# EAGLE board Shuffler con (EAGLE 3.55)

Size 83.49 x 51.42 mm. Coordinates in mm from the lower left corner, seen from the top.
Outline: 43.02,26.03 43.02,27.3
Outline: 43.02,27.3 44.29,27.3 43.02,28.57
Outline: 43.02,28.57 41.75,27.3 43.02,27.3
Outline: 44.29,28.57 43.02,28.57
Outline: 43.02,28.57 41.75,28.57
Outline: 43.02,28.57 43.02,29.84
Outline: 0,0 83.49,0 83.49,51.42 0,51.42 0,0
Outline: 67.78,1.9 67.78,6.98 77.94,6.98 77.94,22.86 66.51,22.86 66.51,29.21 55.08,29.21 55.08,1.9 67.78,1.9
Copper layers used: 

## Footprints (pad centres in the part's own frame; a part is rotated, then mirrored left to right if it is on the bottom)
_PCB = drill 1.016 pad 1.93 square: 0 -5.08,10.16; 1 -2.54,10.16; 2 2.54,10.16; 3 5.08,10.16;  0,0;  -5.08,-2.54;  -7.62,0;  5.08,-2.54;  7.62,0
04-1 = drill 0.813 pad 1.6 octagon:  -3.81,0;  -1.27,0;  1.27,0;  3.81,0
02-1 = drill 0.813 pad 1.6 octagon:  -1.27,0;  1.27,0
03-1 = drill 0.813 pad 1.6 octagon:  -2.54,0;  0,0;  2.54,0
01-1 = drill 0.813 pad 1.6 octagon:  0,0
02-1' = drill 1.016 pad 1.6 round:  -1.27,0 | drill 1.016 pad 1.6 octagon:  1.27,0

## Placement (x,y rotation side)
DIN1  DIN 5p  [_PCB]  11.9,39.36 0 top
DIN2  DIN 5p  [_PCB]  72.86,39.36 0 top
DIN3  DIN 5p  [_PCB]  32.22,39.36 0 top
SV1  FE04-1  [04-1]  60.16,7.61 270 top
SV2  FE04-1  [04-1]  33.49,1.27 180 top
SV3  FE04-1  [04-1]  62.7,22.86 270 top
SV4  FE04-1  [04-1]  75.4,15.24 90 top
SV5  [02-1]  39.84,27.93 90 top
SV6  FE03-1  [03-1]  50,39.36 90 top
SV7  FE01-1  [01-1]  50,44.44 0 top
SV8  MA02-1  [02-1']  6.82,5.07 90 top

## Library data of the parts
DIN1-DIN3 = con-din
SV1-SV7 = CON-LSTA
SV8 = CON-LSTB

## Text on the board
Dimension: GND | Clock | MIDI | BB | LED | 4 | 3 | 2 | 1 | 8 | 7 | 6 | A | 5 | 10 | select | 11 | 2 | 3 | 4 | A | 12 | SRL | POWER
